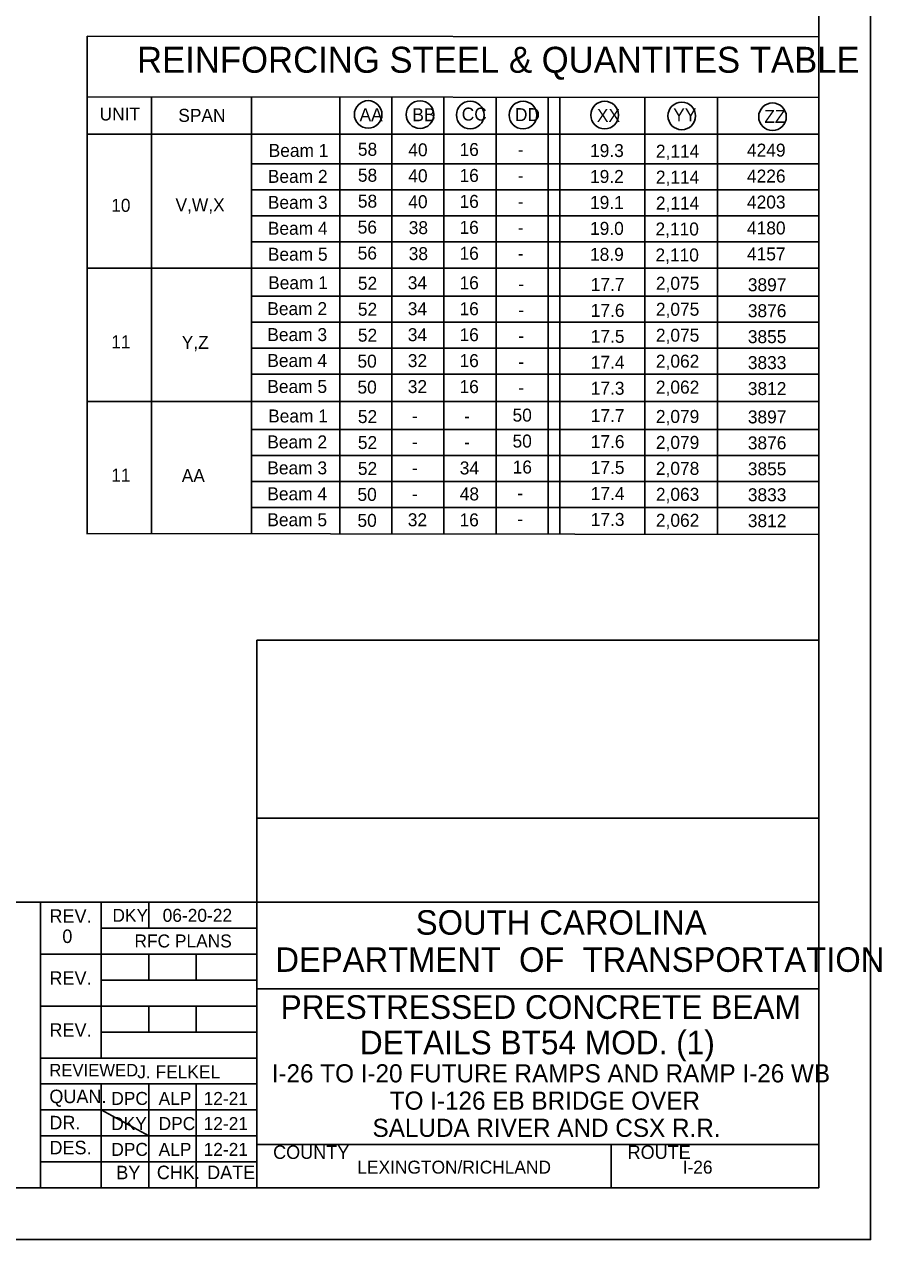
# Model space of a CAD drawing. Extents: x -125.5 to -89.3, y 42.4 to 64.4.
# Drawn here: x -97.69 to -89.43, y 42.45 to 54.16 of the extents above; entities that cross this region are included whole.
import ezdxf

# ---------------------------------------------------------------- set-up
doc = ezdxf.new("R2010")
doc.units = 0
for name, color, linetype in [('BR_AUTO DIMENSION', 7, 'Continuous'), ('BR_BORDER LINES', 7, 'Continuous'), ('BR_TABLE LINES', 7, 'Continuous'), ('BR_TEXT', 7, 'Continuous'), ('Level 31', 7, 'Continuous')]:
    doc.layers.add(name, color=color, linetype=linetype)

msp = doc.modelspace()

# ---------------------------------------------------------------- linework, layer by layer
at = {"layer": 'BR_AUTO DIMENSION'}
for centre in [(-94.377, 53.289), (-93.877, 53.288), (-93.393, 53.284), (-92.884, 53.283), (-92.097, 53.283), (-91.354, 53.275), (-90.479, 53.267)]:
    msp.add_circle(centre, 0.133, dxfattribs=at)
at = {"layer": 'BR_BORDER LINES'}
for p, q in [((-90.033, 42.949), (-90.033, 63.949)), ((-97.087, 54.044), (-97.087, 49.251)), ((-97.087, 54.044), (-90.033, 54.037)), ((-97.087, 53.459), (-90.033, 53.453)), ((-97.087, 53.459), (-97.087, 49.251)), ((-92.642, 53.453), (-92.642, 49.249)), ((-92.528, 53.453), (-92.528, 49.248)), ((-90.033, 53.451), (-90.033, 49.246)), ((-97.092, 49.251), (-90.033, 49.244)), ((-95.45, 42.949), (-95.45, 48.225)), ((-95.45, 48.225), (-90.033, 48.225)), ((-95.45, 46.51), (-90.033, 46.51)), ((-102.899, 45.699), (-97.534, 45.699)), ((-97.534, 42.949), (-97.534, 45.699)), ((-97.534, 45.699), (-90.033, 45.699)), ((-96.95, 45.699), (-96.95, 44.199)), ((-96.492, 45.449), (-96.492, 45.699)), ((-96.95, 45.449), (-95.45, 45.449)), ((-97.534, 45.199), (-95.45, 45.199)), ((-96.492, 44.949), (-96.492, 45.199)), ((-96.034, 44.949), (-96.034, 45.199)), ((-96.95, 44.949), (-95.45, 44.949)), ((-95.45, 44.865), (-95.45, 44.865)), ((-95.45, 44.865), (-90.033, 44.865)), ((-97.534, 44.699), (-95.45, 44.699)), ((-96.492, 44.449), (-96.492, 44.699)), ((-96.034, 44.449), (-96.034, 44.699)), ((-96.95, 44.449), (-95.45, 44.449)), ((-97.534, 44.199), (-95.45, 44.199)), ((-97.534, 43.949), (-95.45, 43.949)), ((-96.95, 43.949), (-96.95, 42.949)), ((-96.492, 43.949), (-96.492, 42.949)), ((-96.034, 43.949), (-96.034, 42.949)), ((-97.534, 43.699), (-95.45, 43.699)), ((-97.534, 43.449), (-95.45, 43.449)), ((-95.45, 43.365), (-90.033, 43.365)), ((-95.353, 43.365), (-90.033, 43.365)), ((-92.033, 42.949), (-92.033, 43.365)), ((-97.534, 43.199), (-95.45, 43.199)), ((-123.699, 42.949), (-90.033, 42.949))]:
    msp.add_line(p, q, dxfattribs=at)
at = {"layer": 'BR_TABLE LINES'}
for p, q in [((-96.466, 53.458), (-96.466, 49.25)), ((-95.502, 53.457), (-95.502, 49.249)), ((-94.65, 53.457), (-94.65, 49.248)), ((-94.65, 53.457), (-94.65, 49.248)), ((-94.148, 53.456), (-94.148, 49.248)), ((-93.646, 53.455), (-93.646, 49.248)), ((-93.144, 53.454), (-93.144, 49.247)), ((-92.642, 53.453), (-92.642, 49.247)), ((-92.642, 53.453), (-92.642, 49.249)), ((-91.71, 53.452), (-91.71, 49.248)), ((-91.01, 53.452), (-91.01, 49.247)), ((-97.087, 53.1), (-90.033, 53.1)), ((-95.502, 52.812), (-90.033, 52.812)), ((-95.502, 52.562), (-90.033, 52.562)), ((-95.502, 52.312), (-90.033, 52.312)), ((-95.502, 52.062), (-90.033, 52.062)), ((-97.087, 51.809), (-90.033, 51.809)), ((-95.507, 51.538), (-90.033, 51.538)), ((-95.507, 51.288), (-90.033, 51.288)), ((-95.507, 51.038), (-90.033, 51.038)), ((-95.507, 50.788), (-90.033, 50.788)), ((-97.087, 50.525), (-90.033, 50.525)), ((-95.507, 50.254), (-90.033, 50.254)), ((-95.507, 50.004), (-90.033, 50.004)), ((-95.507, 49.754), (-90.033, 49.754)), ((-95.502, 49.504), (-90.033, 49.504))]:
    msp.add_line(p, q, dxfattribs=at)
at = {"layer": 'Level 31'}
for p, q in [((-92.742, 44.425), (-92.742, 44.425)), ((-96.95, 43.699), (-96.492, 43.449))]:
    msp.add_line(p, q, dxfattribs=at)
msp.add_lwpolyline([(-125.533, 42.449), (-89.533, 42.449), (-89.533, 64.449), (-125.533, 64.449)], close=True, dxfattribs=at)

# ---------------------------------------------------------------- texts
at = {"layer": 'BR_AUTO DIMENSION'}
for s, p in [('58', (-94.476, 52.891)), ('40', (-93.99, 52.886)), ('16', (-93.496, 52.889)), ('-', (-92.935, 52.888)), ('2,114', (-91.603, 52.873)), ('58', (-94.476, 52.641)), ('40', (-93.99, 52.636)), ('16', (-93.496, 52.639)), ('-', (-92.935, 52.638)), ('2,114', (-91.603, 52.623)), ('58', (-94.476, 52.391)), ('40', (-93.99, 52.386)), ('16', (-93.496, 52.389)), ('2,114', (-91.603, 52.373)), ('-', (-92.935, 52.388)), ('56', (-94.478, 52.141)), ('38', (-93.986, 52.136)), ('16', (-93.496, 52.139)), ('2,110', (-91.607, 52.123)), ('-', (-92.935, 52.138)), ('56', (-94.478, 51.891)), ('38', (-93.986, 51.886)), ('16', (-93.496, 51.889)), ('2,110', (-91.607, 51.873)), ('-', (-92.935, 51.888)), ('52', (-94.476, 51.6)), ('34', (-93.995, 51.605)), ('16', (-93.496, 51.605)), ('-', (-92.929, 51.595)), ('2,075', (-91.603, 51.6)), ('52', (-94.476, 51.35)), ('34', (-93.995, 51.355)), ('16', (-93.496, 51.355)), ('2,075', (-91.603, 51.35)), ('-', (-92.929, 51.345)), ('52', (-94.476, 51.1)), ('34', (-93.995, 51.105)), ('16', (-93.496, 51.105)), ('2,075', (-91.603, 51.1)), ('-', (-92.929, 51.095)), ('50', (-94.48, 50.85)), ('32', (-93.995, 50.855)), ('16', (-93.496, 50.855)), ('2,062', (-91.603, 50.85)), ('-', (-92.929, 50.845)), ('50', (-94.48, 50.6)), ('32', (-93.995, 50.605)), ('16', (-93.496, 50.605)), ('2,062', (-91.603, 50.6)), ('-', (-92.929, 50.595)), ('52', (-94.476, 50.316)), ('-', (-93.954, 50.322)), ('-', (-93.452, 50.321)), ('50', (-92.985, 50.33)), ('2,079', (-91.603, 50.317)), ('52', (-94.476, 50.066)), ('-', (-93.954, 50.072)), ('-', (-93.452, 50.071)), ('50', (-92.985, 50.08)), ('2,079', (-91.603, 50.067)), ('52', (-94.476, 49.816)), ('34', (-93.494, 49.821)), ('16', (-92.984, 49.83)), ('2,078', (-91.603, 49.817)), ('-', (-93.954, 49.822)), ('50', (-94.48, 49.566)), ('48', (-93.494, 49.571)), ('2,063', (-91.603, 49.567)), ('-', (-93.954, 49.572)), ('-', (-92.94, 49.58)), ('50', (-94.48, 49.316)), ('32', (-93.995, 49.322)), ('16', (-93.496, 49.321)), ('2,062', (-91.603, 49.317)), ('-', (-92.94, 49.33))]:
    msp.add_text(s, height=0.125, dxfattribs=at).set_placement(p)
at = {"layer": 'BR_TEXT'}
for s, height, p in [('REINFORCING STEEL & QUANTITES TABLE', 0.25, (-96.605, 53.691)), ('CC', 0.125, (-93.475, 53.23)), ('DD', 0.125, (-92.962, 53.225)), ('YY', 0.125, (-91.436, 53.222)), ('ZZ', 0.125, (-90.558, 53.208)), ('Beam 1', 0.125, (-95.336, 52.88)), ('19.3', 0.125, (-92.238, 52.879)), ('Beam 2', 0.125, (-95.344, 52.63)), ('19.2', 0.125, (-92.238, 52.629)), ('Beam 3', 0.125, (-95.344, 52.38)), ('19.1', 0.125, (-92.238, 52.379)), ('Beam 4', 0.125, (-95.344, 52.13)), ('19.0', 0.125, (-92.238, 52.129)), ('Beam 5', 0.125, (-95.344, 51.88)), ('18.9', 0.125, (-92.238, 51.879)), ('Beam 1', 0.125, (-95.341, 51.606)), ('Beam 2', 0.125, (-95.349, 51.356)), ('Beam 3', 0.125, (-95.349, 51.106)), ('Beam 4', 0.125, (-95.349, 50.856)), ('Beam 5', 0.125, (-95.349, 50.606)), ('Beam 1', 0.125, (-95.341, 50.322)), ('Beam 2', 0.125, (-95.349, 50.072)), ('Beam 3', 0.125, (-95.349, 49.822)), ('Beam 4', 0.125, (-95.349, 49.572)), ('Beam 5', 0.125, (-95.349, 49.322)), ('REV.', 0.13, (-97.449, 45.502)), ('DKY', 0.125, (-96.842, 45.511)), ('06-20-22', 0.125, (-96.358, 45.511)), ('SOUTH CAROLINA', 0.23587, (-93.918, 45.387)), ('0', 0.13, (-97.325, 45.307)), ('RFC PLANS', 0.125, (-96.63, 45.264)), ('DEPARTMENT  OF  TRANSPORTATION', 0.23587, (-95.271, 45.029)), ('REV.', 0.13, (-97.449, 44.904)), ('PRESTRESSED CONCRETE BEAM ', 0.228, (-95.221, 44.576)), ('REV.', 0.13, (-97.449, 44.404)), ('DETAILS BT54 MOD. (1)', 0.228, (-94.457, 44.234)), ('REVIEWED', 0.12, (-97.45, 44.022)), ('J. FELKEL', 0.125, (-96.603, 44.003)), ('I-26 TO I-20 FUTURE RAMPS AND RAMP I-26 WB', 0.175, (-95.307, 43.964)), ('QUAN.', 0.13, (-97.45, 43.764)), ('DPC', 0.125, (-96.853, 43.747)), ('ALP', 0.125, (-96.397, 43.747)), ('12-21', 0.125, (-95.963, 43.747)), ('TO I-126 EB BRIDGE OVER', 0.175, (-94.169, 43.701)), ('DR.', 0.13, (-97.45, 43.512)), ('DKY', 0.125, (-96.854, 43.505)), ('DPC', 0.125, (-96.397, 43.505)), ('12-21', 0.125, (-95.963, 43.505)), ('SALUDA RIVER AND CSX R.R.', 0.175, (-94.335, 43.439)), ('DES.', 0.13, (-97.449, 43.271)), ('DPC', 0.125, (-96.853, 43.256)), ('ALP', 0.125, (-96.397, 43.256)), ('12-21', 0.125, (-95.963, 43.256)), ('COUNTY', 0.13, (-95.293, 43.227)), ('ROUTE', 0.13, (-91.876, 43.227)), ('LEXINGTON/RICHLAND', 0.12499, (-94.481, 43.085)), ('I-26', 0.125, (-91.345, 43.085)), ('BY', 0.13, (-96.805, 43.031)), ('CHK.', 0.13, (-96.414, 43.032)), ('DATE', 0.13, (-95.929, 43.032))]:
    msp.add_text(s, height=height, dxfattribs=at).set_placement(p)
for s, p in [('UNIT', (-96.966, 53.231)), ('UNIT', (-96.966, 53.231)), ('SPAN', (-96.207, 53.218)), ('AA', (-94.46, 53.224)), ('BB', (-93.951, 53.224)), ('XX', (-92.172, 53.218)), ('4249', (-90.725, 52.883)), ('4226', (-90.725, 52.633)), ('10', (-96.854, 52.351)), ('V,W,X', (-96.234, 52.355)), ('4203', (-90.725, 52.383)), ('4180', (-90.725, 52.133)), ('4157', (-90.725, 51.883)), ('17.7', (-92.231, 51.589)), ('3897', (-90.717, 51.586)), ('17.6', (-92.231, 51.339)), ('3876', (-90.717, 51.336)), ('17.5', (-92.231, 51.089)), ('3855', (-90.717, 51.086)), ('11', (-96.854, 51.036)), ('Y,Z', (-96.174, 51.031)), ('17.4', (-92.231, 50.839)), ('3833', (-90.717, 50.836)), ('17.3', (-92.231, 50.589)), ('3812', (-90.717, 50.586)), ('17.7', (-92.231, 50.325)), ('3897', (-90.717, 50.313)), ('17.6', (-92.231, 50.075)), ('3876', (-90.717, 50.063)), ('17.5', (-92.231, 49.825)), ('3855', (-90.717, 49.813)), ('11', (-96.854, 49.752)), ('AA', (-96.174, 49.747)), ('17.4', (-92.231, 49.575)), ('3833', (-90.717, 49.563)), ('17.3', (-92.231, 49.325)), ('3812', (-90.717, 49.313))]:
    msp.add_text(s, height=0.125, rotation=360, dxfattribs=at).set_placement(p)

doc.saveas('drawing.dxf')
